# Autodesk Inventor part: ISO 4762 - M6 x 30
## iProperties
Comments: To add or edit properties for Autodesk Inventor files, use iProperties.
Created: 2004-08
Part Number: ISO 4762 - M6 x 30
Vendor: Autodesk Inc.
Document SubType Name: Modeling
Designer: John Blackburn
Material: Default
Description: Hexagon Socket Head Cap Screw
Standard: ISO 4762
Alert: To add or edit properties for Autodesk Inventor files, use iProperties.
Control State: 0
Master: False
Checked Out: False
Shininess: 64.0
Length Units: 11269
Angle Units: 11279
Time Units: 11290
Mass Units: 11283
Length Display Precision: 3
Angle Display Precision: 2
Compacted: True
EGR: 1
Density: 0.0
Volumn: 0.0
Area: 0.0
PropertySet Name: Model Information
Author: John Blackburn
Revision Number: 8
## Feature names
1. Body [Revolution]
2. Slot [Extrusion]
3. Fillet1
4. Chamfer1
